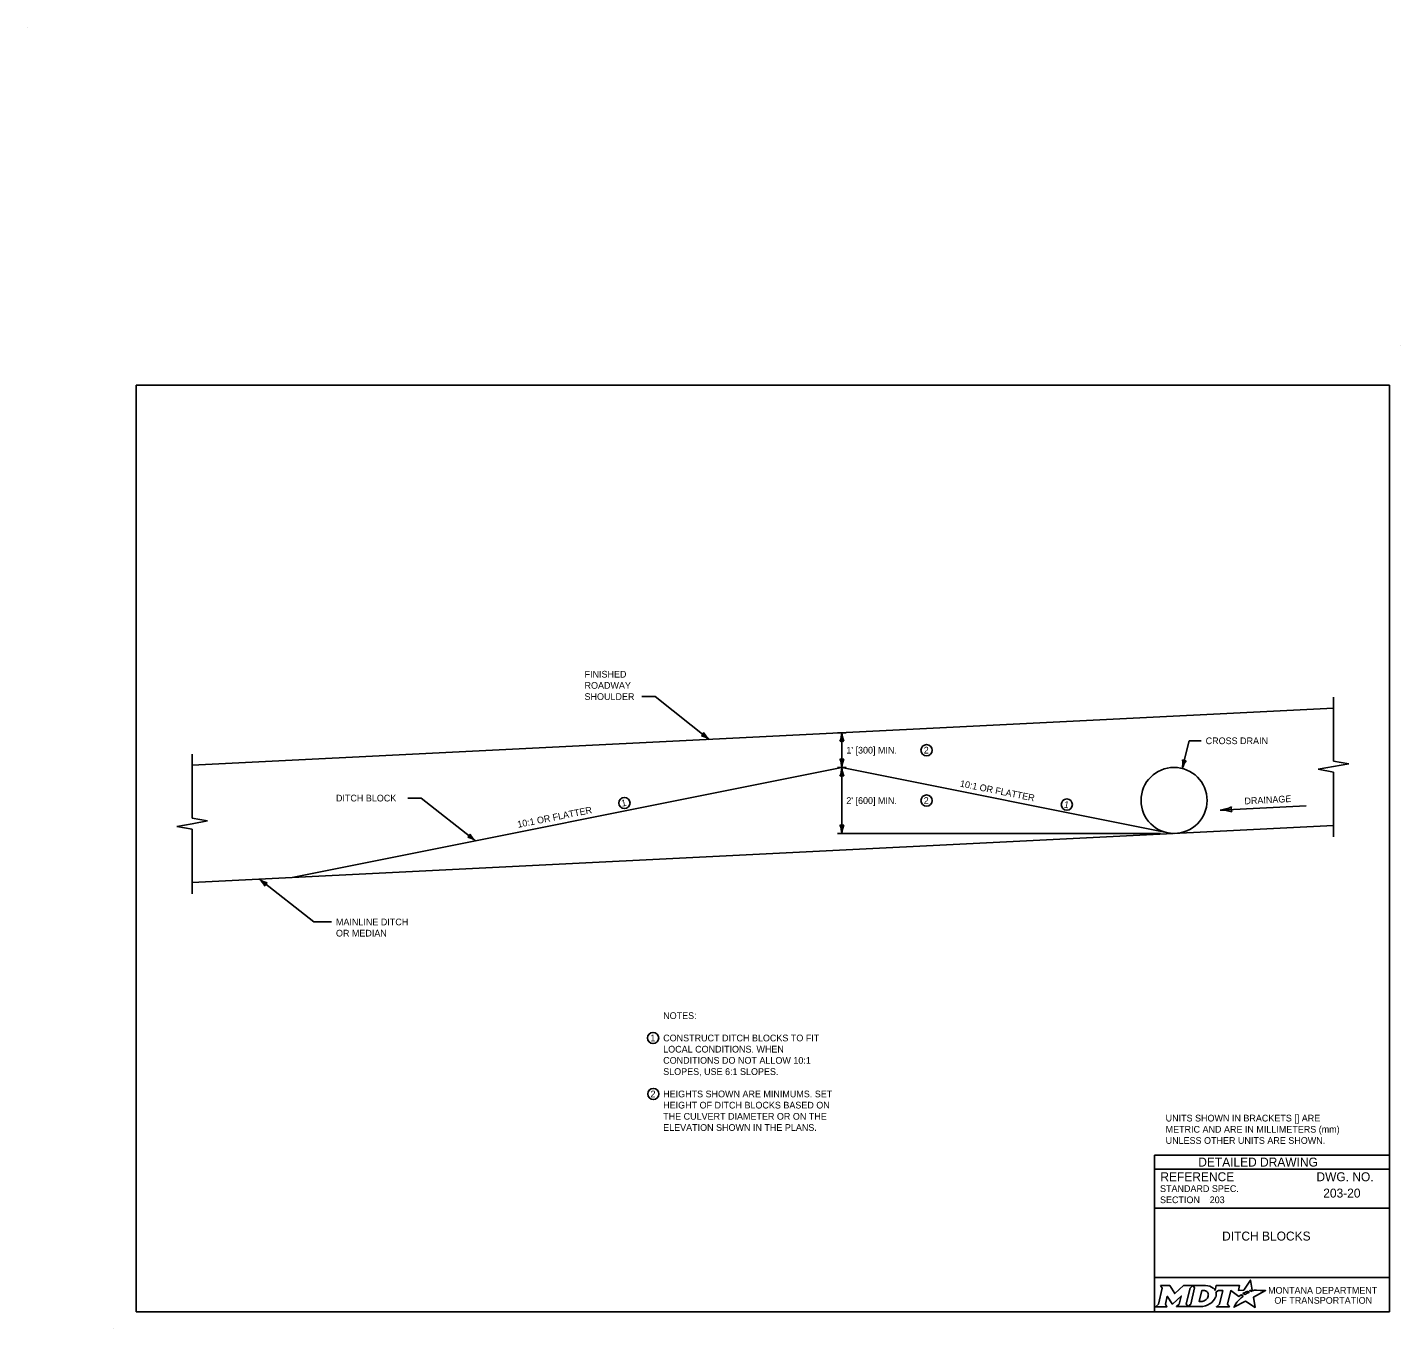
# Model space of a CAD drawing. Extents: x 49991.4 to 50021, y 49987.6 to 50011.4.
# Drawn here: x 50008.76 to 50021.04, y 49999.74 to 50011.36 of the extents above; entities that cross this region are included whole.
import ezdxf

# ---------------------------------------------------------------- set-up
doc = ezdxf.new("R2010")
doc.units = 0
for name, color, linetype in [('Default', 7, 'Continuous'), ('Level 1', 7, 'Continuous'), ('Level 2', 7, 'Continuous'), ('Level 3', 7, 'Continuous'), ('Level 4', 7, 'Continuous'), ('Level 6', 7, 'Continuous')]:
    doc.layers.add(name, color=color, linetype=linetype)

msp = doc.modelspace()

# ---------------------------------------------------------------- linework, layer by layer
at = {"layer": 'Default'}
for points in [[(50018.893, 50000.121), (50018.907, 50000.097), (50018.874, 49999.954), (50018.848, 49999.931), (50018.95, 49999.931), (50018.936, 49999.954), (50018.952, 50000.024), (50018.996, 49999.955), (50019.002, 49999.955), (50019.077, 50000.025), (50019.06, 49999.954), (50019.035, 49999.932), (50019.137, 49999.932), (50019.123, 49999.955), (50019.156, 50000.097)], [(50019.156, 50000.097), (50019.182, 50000.121), (50019.099, 50000.121), (50019.02, 50000.048), (50018.975, 50000.12), (50018.893, 50000.121)], [(50019.295, 50000.121), (50019.182, 50000.121), (50019.196, 50000.098), (50019.163, 49999.954), (50019.137, 49999.932), (50019.248, 49999.932)], [(50019.7, 50000.068), (50019.69, 50000.074), (50019.702, 50000.076), (50019.713, 50000.078), (50019.696, 50000.168), (50019.636, 50000.077), (50019.589, 50000.076), (50019.599, 50000.12), (50019.39, 50000.121), (50019.38, 50000.078), (50019.374, 50000.086)], [(50019.319, 50000.034), (50019.318, 50000.026), (50019.315, 50000.017), (50019.311, 50000.008), (50019.305, 50000.001), (50019.299, 49999.994), (50019.291, 49999.988), (50019.282, 49999.983), (50019.273, 49999.979), (50019.264, 49999.977), (50019.255, 49999.976), (50019.239, 49999.976), (50019.263, 50000.076), (50019.279, 50000.076), (50019.286, 50000.075), (50019.294, 50000.073), (50019.301, 50000.07), (50019.307, 50000.066), (50019.311, 50000.061), (50019.315, 50000.055), (50019.318, 50000.049), (50019.319, 50000.042), (50019.32, 50000.038), (50019.319, 50000.034)], [(50019.387, 50000.062), (50019.411, 50000.075), (50019.448, 50000.075), (50019.42, 49999.954), (50019.392, 49999.931), (50019.508, 49999.931), (50019.491, 49999.954), (50019.52, 50000.075), (50019.591, 50000.023), (50019.612, 50000.038), (50019.632, 50000.027)], [(50019.576, 49999.971), (50019.561, 49999.947), (50019.556, 49999.939), (50019.55, 49999.931), (50019.548, 49999.926), (50019.653, 49999.979), (50019.737, 49999.924), (50019.724, 50000.017), (50019.831, 50000.075), (50019.782, 50000.076), (50019.751, 50000.077), (50019.731, 50000.077), (50019.724, 50000.075), (50019.719, 50000.074), (50019.711, 50000.072), (50019.7, 50000.068)], [(50019.59, 49999.987), (50019.59, 49999.987)], [(50019.65, 50000.04), (50019.648, 50000.039), (50019.629, 50000.048), (50019.639, 50000.054), (50019.644, 50000.056), (50019.652, 50000.06), (50019.658, 50000.063), (50019.666, 50000.066), (50019.673, 50000.068), (50019.685, 50000.061), (50019.681, 50000.059), (50019.676, 50000.056), (50019.672, 50000.054), (50019.667, 50000.051), (50019.665, 50000.05), (50019.662, 50000.049), (50019.66, 50000.047), (50019.658, 50000.046), (50019.655, 50000.044), (50019.652, 50000.042), (50019.65, 50000.04)], [(50019.293, 49999.939), (50019.302, 49999.942), (50019.315, 49999.947), (50019.335, 49999.958)]]:
    msp.add_lwpolyline(points, dxfattribs=at)
for centre, radius, start, end in [((50019.274, 50000.059), 0.118, 300.9103, 339.1383), ((50019.319, 50000.042), 0.0709, 339.5329, 15.8582)]:
    msp.add_arc(centre, radius, start, end, dxfattribs=at)
for centre, major_axis, ratio, start_param, end_param in [((50019.293, 50000.073), (0.0834, -0.0037), 0.568097, 0.61298, 1.570796), ((50019.349, 50000.081), (0.0361, -0.0295), 0.469099, 1.225588, 1.570796), ((50019.583, 49999.979), (-0.00694, -0.00806), 0.008222, 0, 3.137361), ((50019.6, 49999.997), (-0.0098, -0.0102), 0.016458, 3.141593, 6.279097), ((50019.621, 50000.017), (-0.0112, -0.0097), 0.021651, 3.157348, 6.283185), ((50019.248, 50000.08), (0, 0.148), 0.987302, 3.139398, 3.456847)]:
    msp.add_ellipse(centre, major_axis=major_axis, ratio=ratio, start_param=start_param, end_param=end_param, dxfattribs=at)
at = {"layer": 'Level 1'}
for p, q in [((50008.765, 50011.363), (50008.765, 50011.363)), ((50021.038, 50008.524), (50021.038, 50008.524)), ((50020.438, 50005.279), (50010.237, 50004.769)), ((50016.044, 50004.748), (50011.132, 50003.766)), ((50018.992, 50004.159), (50016.044, 50004.748)), ((50020.438, 50004.231), (50010.237, 50003.721)), ((50009.537, 49999.736), (50009.537, 49999.736))]:
    msp.add_line(p, q, dxfattribs=at)
msp.add_lwpolyline([(50020.938, 50008.165), (50009.737, 50008.165), (50009.737, 49999.886), (50020.938, 49999.886)], close=True, dxfattribs=at)
msp.add_circle((50019.013, 50004.455), 0.295, dxfattribs=at)
at = {"layer": 'Level 2'}
for centre in [(50016.801, 50004.904), (50014.101, 50004.432), (50016.801, 50004.454), (50018.055, 50004.418), (50014.357, 50002.332), (50014.359, 50001.832)]:
    msp.add_circle(centre, 0.05, dxfattribs=at)
at = {"layer": 'Level 3'}
for p, q in [((50014.374, 50005.383), (50014.255, 50005.383)), ((50014.859, 50005), (50014.374, 50005.383)), ((50016.004, 50005.06), (50016.084, 50005.06)), ((50016.044, 50004.748), (50016.044, 50005.06)), ((50019.087, 50004.741), (50019.149, 50004.988)), ((50019.149, 50004.988), (50019.256, 50004.988)), ((50016.004, 50004.748), (50016.084, 50004.748)), ((50016.044, 50004.748), (50016.044, 50004.159)), ((50012.285, 50004.476), (50012.166, 50004.476)), ((50012.77, 50004.093), (50012.285, 50004.476)), ((50020.195, 50004.408), (50019.426, 50004.369)), ((50018.892, 50004.159), (50016.004, 50004.159)), ((50010.838, 50003.751), (50011.324, 50003.369)), ((50011.324, 50003.369), (50011.482, 50003.369))]:
    msp.add_line(p, q, dxfattribs=at)
for centre, radius, start, end in [((50014.758, 50005.08), 0.0548, 303.8953, 339.6177), ((50014.724, 50004.81), 0.233, 54.5838, 73.8336), ((50015.004, 50005.169), 0.222, 209.2125, 229.396), ((50015.822, 50005.069), 0.222, 337.456, 357.6395), ((50016.277, 50005.071), 0.233, 182.8273, 202.0772), ((50016.044, 50004.931), 0.0548, 72.1388, 107.8612), ((50016.044, 50004.877), 0.0548, 252.1388, 287.8612), ((50015.811, 50004.737), 0.233, 2.8273, 22.0772), ((50016.266, 50004.739), 0.222, 157.456, 177.6395), ((50018.858, 50004.786), 0.233, 348.6361, 7.886), ((50019.3, 50004.677), 0.222, 143.2648, 163.4484), ((50019.118, 50004.865), 0.0548, 237.9477, 273.67), ((50015.822, 50004.757), 0.222, 337.456, 357.6395), ((50016.044, 50004.62), 0.0548, 72.1388, 107.8612), ((50016.277, 50004.76), 0.233, 182.8273, 202.0772), ((50019.395, 50004.679), 0.311, 275.6897, 294.9396), ((50019.597, 50004.378), 0.073, 165.0012, 200.7236), ((50019.429, 50004.073), 0.296, 70.3184, 90.5019), ((50012.669, 50004.173), 0.0548, 303.8953, 339.6177), ((50012.915, 50004.262), 0.222, 209.2125, 229.396), ((50016.044, 50004.287), 0.0548, 252.1388, 287.8612), ((50015.811, 50004.147), 0.233, 2.8273, 22.0772), ((50016.266, 50004.15), 0.222, 157.456, 177.6395), ((50012.635, 50003.904), 0.233, 54.5838, 73.8336), ((50010.694, 50003.582), 0.222, 29.2125, 49.396), ((50010.973, 50003.941), 0.233, 234.5838, 253.8336), ((50010.939, 50003.672), 0.0548, 123.8953, 159.6177)]:
    msp.add_arc(centre, radius, start, end, dxfattribs=at)
at = {"layer": 'Level 4'}
for p, q in [((50020.938, 50001.286), (50018.838, 50001.286)), ((50018.838, 50001.286), (50018.838, 49999.886)), ((50020.938, 50001.161), (50018.838, 50001.161)), ((50019.332, 50000.886), (50019.332, 50000.886)), ((50020.574, 50000.946), (50020.574, 50000.946)), ((50020.938, 50000.811), (50018.838, 50000.811)), ((50019.888, 50000.562), (50019.888, 50000.562)), ((50020.938, 50000.193), (50018.838, 50000.193))]:
    msp.add_line(p, q, dxfattribs=at)
at = {"layer": 'Level 6'}
for p, q in [((50020.438, 50004.806), (50020.438, 50005.379)), ((50010.237, 50004.296), (50010.237, 50004.869)), ((50020.301, 50004.733), (50020.438, 50004.758)), ((50020.438, 50004.806), (50020.576, 50004.782)), ((50020.438, 50004.758), (50020.576, 50004.782)), ((50020.301, 50004.733), (50020.438, 50004.709)), ((50020.438, 50004.709), (50020.438, 50004.131)), ((50010.237, 50004.296), (50010.374, 50004.272)), ((50010.237, 50004.247), (50010.374, 50004.272)), ((50010.099, 50004.223), (50010.237, 50004.247)), ((50010.099, 50004.223), (50010.237, 50004.199)), ((50010.237, 50004.199), (50010.237, 50003.621))]:
    msp.add_line(p, q, dxfattribs=at)

# ---------------------------------------------------------------- texts
at = {"layer": 'Default'}
for s, p in [('MONTANA DEPARTMENT', (50019.854, 50000.047)), ('OF TRANSPORTATION', (50019.91, 49999.957))]:
    msp.add_text(s, height=0.06, dxfattribs=at).set_placement(p)
at = {"layer": 'Level 2'}
for s, height, p in [('FINISHED', 0.06, (50013.744, 50005.553)), ('ROADWAY', 0.06, (50013.744, 50005.453)), ('SHOULDER', 0.06, (50013.744, 50005.353)), ('CROSS DRAIN', 0.06, (50019.296, 50004.958)), ("1' [300] MIN.", 0.06, (50016.084, 50004.874)), ('2', 0.06, (50016.776, 50004.874)), ('DITCH BLOCK', 0.06, (50011.522, 50004.446)), ("2' [600] MIN.", 0.06, (50016.084, 50004.424)), ('2', 0.06, (50016.776, 50004.424)), ('OR MEDIAN', 0.06, (50011.522, 50003.239)), ('MAINLINE DITCH', 0.06, (50011.522, 50003.339)), ('NOTES:', 0.06, (50014.447, 50002.502)), ('1', 0.06, (50014.332, 50002.302)), ('CONSTRUCT DITCH BLOCKS TO FIT', 0.06, (50014.447, 50002.302)), ('LOCAL CONDITIONS. WHEN ', 0.06, (50014.447, 50002.202)), ('CONDITIONS DO NOT ALLOW 10:1', 0.06, (50014.447, 50002.102)), ('SLOPES, USE 6:1 SLOPES.', 0.06, (50014.447, 50002.002)), ('2', 0.06, (50014.334, 50001.802)), ('HEIGHTS SHOWN ARE MINIMUMS. SET', 0.06, (50014.447, 50001.802)), ('HEIGHT OF DITCH BLOCKS BASED ON', 0.06, (50014.447, 50001.702)), ('THE CULVERT DIAMETER OR ON THE ', 0.06, (50014.447, 50001.602)), ('UNITS SHOWN IN BRACKETS [] ARE ', 0.06, (50018.938, 50001.586)), ('ELEVATION SHOWN IN THE PLANS.', 0.06, (50014.447, 50001.502)), ('METRIC AND ARE IN MILLIMETERS (mm) ', 0.06, (50018.938, 50001.486)), ('UNLESS OTHER UNITS ARE SHOWN.', 0.06, (50018.938, 50001.386)), ('203-20', 0.08, (50020.347, 50000.906)), ('203', 0.06, (50019.332, 50000.856)), ('DITCH BLOCKS', 0.08, (50019.443, 50000.522))]:
    msp.add_text(s, height=height, dxfattribs=at).set_placement(p)
for s, rotation, p in [('10:1 OR FLATTER', 348.6912, (50017.096, 50004.579)), ('10:1 OR FLATTER', 11.3088, (50013.15, 50004.21)), ('1', 11.3099, (50014.079, 50004.399)), ('1', 348.6901, (50018.025, 50004.393)), ('DRAINAGE', 2.8624, (50019.644, 50004.42))]:
    msp.add_text(s, height=0.06, rotation=rotation, dxfattribs=at).set_placement(p)
at = {"layer": 'Level 4'}
for s, height, p in [('DETAILED DRAWING', 0.0799, (50019.23, 50001.183)), ('REFERENCE', 0.08, (50018.891, 50001.052)), ('DWG. NO.', 0.08, (50020.286, 50001.052)), ('STANDARD SPEC.', 0.06, (50018.888, 50000.956)), ('SECTION', 0.06, (50018.888, 50000.856))]:
    msp.add_text(s, height=height, dxfattribs=at).set_placement(p)

doc.saveas('drawing.dxf')
